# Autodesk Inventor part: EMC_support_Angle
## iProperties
Shininess: 64.0
Length Units: 11269
Angle Units: 11279
Time Units: 11290
Mass Units: 11283
Length Display Precision: 3
Angle Display Precision: 2
Compacted: True
Part Number: EMC_support_Angle
Document SubType Name: Modeling
Created: 2004-08
Material: Aluminum-6061
Designer: John Blackburn
Manufacturer: Standard
Standards Organization: Custom
Density: 0.0
Volumn: 0.0
Area: 0.0
PropertySet Name: Model Information
Control State: 0
Master: False
Checked Out: False
Author: John Blackburn
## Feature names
1. Extrusion1
2. Chamfer1
3. Hole1
4. Extrusion2
5. Extrusion3
